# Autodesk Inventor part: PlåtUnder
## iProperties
Shininess: 64.0
Length Units: 11269
Angle Units: 11279
Time Units: 11290
Mass Units: 11283
Length Display Precision: 3
Angle Display Precision: 2
Compacted: True
Created: 2004-01
Part Number: PlåtUnder
Material: Steel, Mild
Document SubType Name: Modeling
Designer: Administratör
Manufacturer: Standard
Standards Organization: Custom
Density: 0.0
Volumn: 0.0
Area: 0.0
PropertySet Name: Model Information
Control State: 0
Master: False
Checked Out: False
Author: Administratör
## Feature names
1. Extrusion1
